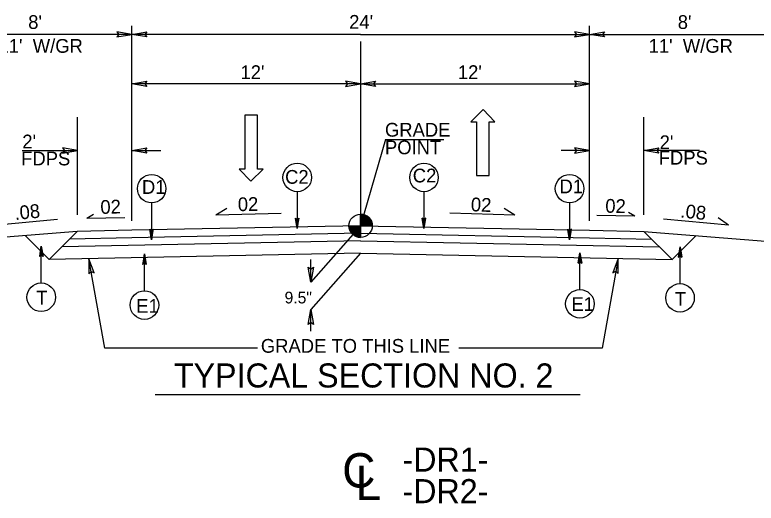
# Model space of a CAD drawing. Extents: x 2532463 to 2534146, y 189689 to 190784.
# Drawn here: x 2533259.8 to 2533701.3, y 189974.2 to 190265.3 of the extents above; entities that cross this region are included whole.
import ezdxf

# ---------------------------------------------------------------- set-up
doc = ezdxf.new("R2010")
doc.units = 0
for name, color, linetype in [('Old_Level_1', 7, 'Continuous'), ('Old_Level_12', 7, 'Continuous'), ('Old_Level_2', 7, 'Continuous'), ('Old_Level_3', 7, 'Continuous'), ('Old_Level_4', 7, 'Continuous'), ('Typical Curb CELL', 7, 'Continuous')]:
    doc.layers.add(name, color=color, linetype=linetype)

msp = doc.modelspace()

# ---------------------------------------------------------------- linework, layer by layer
at = {"layer": 'Old_Level_1'}
for p, q in [((2533465.73, 190146.49), (2533465.72, 190139.54)), ((2533465.72, 190139.54), (2533465.73, 190146.49)), ((2533427.97, 190137.84), (2533426.87, 190144.08)), ((2533426.87, 190144.08), (2533427.97, 190143.26)), ((2533427.03, 190143.96), (2533427.97, 190137.84)), ((2533427.97, 190137.84), (2533427.19, 190143.84)), ((2533427.34, 190143.72), (2533427.97, 190137.84)), ((2533427.97, 190137.84), (2533427.5, 190143.61)), ((2533427.66, 190143.5), (2533427.97, 190137.84)), ((2533427.97, 190137.84), (2533427.81, 190143.38)), ((2533427.97, 190137.84), (2533429.07, 190144.08)), ((2533427.97, 190143.26), (2533429.07, 190144.08)), ((2533427.97, 190137.84), (2533428.92, 190143.96)), ((2533428.76, 190143.84), (2533427.97, 190137.84)), ((2533427.97, 190137.84), (2533428.6, 190143.73)), ((2533428.44, 190143.61), (2533427.97, 190137.84)), ((2533427.97, 190137.84), (2533428.29, 190143.5)), ((2533428.13, 190143.38), (2533427.97, 190137.84)), ((2533427.97, 190143.26), (2533427.97, 190137.84)), ((2533503.48, 190137.84), (2533502.38, 190144.08)), ((2533503.48, 190143.26), (2533502.38, 190144.08)), ((2533503.48, 190137.84), (2533502.53, 190143.96)), ((2533502.69, 190143.84), (2533503.48, 190137.84)), ((2533503.48, 190137.84), (2533502.85, 190143.73)), ((2533503.01, 190143.61), (2533503.48, 190137.84)), ((2533503.48, 190137.84), (2533503.16, 190143.5)), ((2533503.32, 190143.38), (2533503.48, 190137.84)), ((2533503.48, 190137.84), (2533504.58, 190144.08)), ((2533504.58, 190144.08), (2533503.48, 190143.26)), ((2533504.42, 190143.96), (2533503.48, 190137.84)), ((2533503.48, 190137.84), (2533504.26, 190143.84)), ((2533504.11, 190143.72), (2533503.48, 190137.84)), ((2533503.48, 190137.84), (2533503.95, 190143.61)), ((2533503.79, 190143.5), (2533503.48, 190137.84)), ((2533503.48, 190137.84), (2533503.64, 190143.38)), ((2533503.48, 190143.26), (2533503.48, 190137.84)), ((2533465.72, 190139.54), (2533329.41, 190136.82)), ((2533458.78, 190139.54), (2533465.72, 190139.54)), ((2533465.72, 190139.54), (2533465.72, 190132.6)), ((2533472.67, 190139.54), (2533465.72, 190139.54)), ((2533465.72, 190139.54), (2533602.04, 190136.82)), ((2533296.94, 190136.17), (2533218.42, 190129.89)), ((2533265.91, 190133.69), (2533280.19, 190119.41)), ((2533296.94, 190136.17), (2533280.19, 190119.41)), ((2533329.41, 190136.82), (2533296.94, 190136.17)), ((2533465.72, 190135.03), (2533329.41, 190132.31)), ((2533341.26, 190131.18), (2533340.16, 190137.41)), ((2533340.16, 190137.41), (2533341.26, 190136.6)), ((2533340.32, 190137.3), (2533341.26, 190131.18)), ((2533341.26, 190131.18), (2533340.47, 190137.18)), ((2533340.63, 190137.06), (2533341.26, 190131.18)), ((2533341.26, 190131.18), (2533340.79, 190136.95)), ((2533340.94, 190136.84), (2533341.26, 190131.18)), ((2533341.26, 190131.18), (2533341.1, 190136.72)), ((2533341.26, 190131.18), (2533342.36, 190137.41)), ((2533341.26, 190136.6), (2533342.36, 190137.41)), ((2533341.26, 190131.18), (2533342.2, 190137.3)), ((2533342.04, 190137.18), (2533341.26, 190131.18)), ((2533341.26, 190131.18), (2533341.89, 190137.06)), ((2533341.73, 190136.95), (2533341.26, 190131.18)), ((2533341.26, 190131.18), (2533341.57, 190136.84)), ((2533341.42, 190136.72), (2533341.26, 190131.18)), ((2533341.26, 190136.6), (2533341.26, 190131.18)), ((2533465.72, 190135.03), (2533602.04, 190132.31)), ((2533590.19, 190131.18), (2533589.09, 190137.41)), ((2533590.19, 190136.6), (2533589.09, 190137.41)), ((2533590.19, 190131.18), (2533589.25, 190137.3)), ((2533589.4, 190137.18), (2533590.19, 190131.18)), ((2533590.19, 190131.18), (2533589.56, 190137.06)), ((2533589.72, 190136.95), (2533590.19, 190131.18)), ((2533590.19, 190131.18), (2533589.88, 190136.84)), ((2533590.03, 190136.72), (2533590.19, 190131.18)), ((2533590.19, 190131.18), (2533591.29, 190137.41)), ((2533591.29, 190137.41), (2533590.19, 190136.6)), ((2533591.13, 190137.3), (2533590.19, 190131.18)), ((2533590.19, 190131.18), (2533590.97, 190137.18)), ((2533590.82, 190137.06), (2533590.19, 190131.18)), ((2533590.19, 190131.18), (2533590.66, 190136.95)), ((2533590.51, 190136.84), (2533590.19, 190131.18)), ((2533590.19, 190131.18), (2533590.35, 190136.72)), ((2533590.19, 190136.6), (2533590.19, 190131.18)), ((2533602.04, 190136.82), (2533634.51, 190136.17)), ((2533634.51, 190136.17), (2533651.26, 190119.41)), ((2533634.51, 190136.17), (2533713.02, 190129.89)), ((2533665.53, 190133.69), (2533651.26, 190119.41)), ((2533465.72, 190130.56), (2533287.77, 190127)), ((2533329.41, 190132.34), (2533292.37, 190131.6)), ((2533465.72, 190130.56), (2533643.68, 190127)), ((2533602.04, 190132.34), (2533639.08, 190131.6)), ((2533275.46, 190127.42), (2533274.36, 190121.19)), ((2533275.46, 190127.42), (2533274.51, 190121.3)), ((2533274.67, 190121.42), (2533275.46, 190127.42)), ((2533275.46, 190127.42), (2533274.83, 190121.54)), ((2533274.99, 190121.65), (2533275.46, 190127.42)), ((2533275.46, 190127.42), (2533275.14, 190121.76)), ((2533275.3, 190121.88), (2533275.46, 190127.42)), ((2533275.46, 190127.42), (2533276.56, 190121.18)), ((2533276.4, 190121.3), (2533275.46, 190127.42)), ((2533275.46, 190127.42), (2533276.24, 190121.42)), ((2533276.08, 190121.54), (2533275.46, 190127.42)), ((2533275.46, 190127.42), (2533275.93, 190121.65)), ((2533275.77, 190121.76), (2533275.46, 190127.42)), ((2533275.46, 190127.42), (2533275.61, 190121.88)), ((2533275.46, 190122), (2533275.46, 190127.42)), ((2533655.99, 190127.04), (2533654.89, 190120.81)), ((2533655.05, 190120.93), (2533655.99, 190127.04)), ((2533655.99, 190127.04), (2533655.21, 190121.05)), ((2533655.36, 190121.16), (2533655.99, 190127.04)), ((2533655.99, 190127.04), (2533655.52, 190121.28)), ((2533655.68, 190121.39), (2533655.99, 190127.04)), ((2533655.99, 190127.04), (2533655.83, 190121.5)), ((2533655.99, 190127.04), (2533657.09, 190120.81)), ((2533655.99, 190121.62), (2533655.99, 190127.04)), ((2533656.15, 190121.5), (2533655.99, 190127.04)), ((2533655.99, 190127.04), (2533656.31, 190121.39)), ((2533656.46, 190121.28), (2533655.99, 190127.04)), ((2533655.99, 190127.04), (2533656.62, 190121.16)), ((2533656.78, 190121.05), (2533655.99, 190127.04)), ((2533655.99, 190127.04), (2533656.94, 190120.93)), ((2533275.46, 190122), (2533274.36, 190121.19)), ((2533276.56, 190121.18), (2533275.46, 190122)), ((2533465.72, 190123.13), (2533280.19, 190119.41)), ((2533336.98, 190122.73), (2533335.88, 190116.5)), ((2533336.98, 190122.73), (2533336.03, 190116.61)), ((2533336.19, 190116.73), (2533336.98, 190122.73)), ((2533336.98, 190122.73), (2533336.35, 190116.85)), ((2533336.51, 190116.96), (2533336.98, 190122.73)), ((2533336.98, 190122.73), (2533336.66, 190117.07)), ((2533336.82, 190117.19), (2533336.98, 190122.73)), ((2533336.98, 190122.73), (2533338.08, 190116.5)), ((2533337.92, 190116.61), (2533336.98, 190122.73)), ((2533336.98, 190122.73), (2533337.76, 190116.73)), ((2533337.6, 190116.85), (2533336.98, 190122.73)), ((2533336.98, 190122.73), (2533337.45, 190116.96)), ((2533337.29, 190117.07), (2533336.98, 190122.73)), ((2533336.98, 190122.73), (2533337.13, 190117.19)), ((2533336.98, 190117.31), (2533336.98, 190122.73)), ((2533465.72, 190123.13), (2533651.26, 190119.41)), ((2533596.35, 190123.48), (2533595.25, 190117.25)), ((2533595.41, 190117.36), (2533596.35, 190123.48)), ((2533596.35, 190123.48), (2533595.56, 190117.48)), ((2533595.72, 190117.6), (2533596.35, 190123.48)), ((2533596.35, 190123.48), (2533595.88, 190117.71)), ((2533596.03, 190117.82), (2533596.35, 190123.48)), ((2533596.35, 190123.48), (2533596.19, 190117.94)), ((2533596.35, 190123.48), (2533597.45, 190117.25)), ((2533596.35, 190118.06), (2533596.35, 190123.48)), ((2533596.51, 190117.94), (2533596.35, 190123.48)), ((2533596.35, 190123.48), (2533596.66, 190117.82)), ((2533596.82, 190117.71), (2533596.35, 190123.48)), ((2533596.35, 190123.48), (2533596.98, 190117.6)), ((2533597.13, 190117.48), (2533596.35, 190123.48)), ((2533596.35, 190123.48), (2533597.29, 190117.36)), ((2533654.89, 190120.81), (2533655.99, 190121.62)), ((2533655.99, 190121.62), (2533657.09, 190120.81)), ((2533336.98, 190117.31), (2533335.88, 190116.5)), ((2533338.08, 190116.5), (2533336.98, 190117.31)), ((2533595.25, 190117.25), (2533596.35, 190118.06)), ((2533596.35, 190118.06), (2533597.45, 190117.25)), ((2533343.32, 190039), (2533596.51, 190039))]:
    msp.add_line(p, q, dxfattribs=at)
for points in [[(2533465.82, 190139.54), (2533465.82, 190146.49), (2533465.82, 190146.49)], [(2533465.96, 190139.54), (2533465.96, 190146.48)], [(2533466.1, 190139.54), (2533466.1, 190146.47)], [(2533466.24, 190139.54), (2533466.24, 190146.47)], [(2533466.37, 190139.54), (2533466.38, 190146.46)], [(2533466.52, 190139.54), (2533466.52, 190146.44)], [(2533466.65, 190139.54), (2533466.65, 190146.43)], [(2533466.8, 190139.54), (2533466.8, 190146.4)], [(2533466.93, 190139.54), (2533466.93, 190146.38)], [(2533467.07, 190139.54), (2533467.07, 190146.36)], [(2533467.21, 190139.54), (2533467.21, 190146.33)], [(2533467.35, 190139.54), (2533467.35, 190146.29)], [(2533467.49, 190139.54), (2533467.49, 190146.26)], [(2533467.63, 190139.54), (2533467.63, 190146.22)], [(2533467.77, 190139.54), (2533467.77, 190146.18)], [(2533467.9, 190139.54), (2533467.9, 190146.14)], [(2533468.04, 190139.54), (2533468.04, 190146.09)], [(2533468.18, 190139.54), (2533468.18, 190146.04)], [(2533468.32, 190139.54), (2533468.32, 190145.98)], [(2533468.46, 190139.54), (2533468.46, 190145.93)], [(2533468.6, 190139.54), (2533468.6, 190145.86)], [(2533468.74, 190139.54), (2533468.74, 190145.8)], [(2533468.88, 190139.54), (2533468.88, 190145.73)], [(2533469.02, 190139.54), (2533469.02, 190145.66)], [(2533469.15, 190139.54), (2533469.15, 190145.58)], [(2533469.29, 190139.54), (2533469.3, 190145.5)], [(2533469.43, 190139.54), (2533469.43, 190145.41)], [(2533469.57, 190139.54), (2533469.57, 190145.32)], [(2533469.71, 190139.54), (2533469.71, 190145.23)], [(2533469.85, 190139.54), (2533469.85, 190145.13)], [(2533469.99, 190139.54), (2533469.99, 190145.02)], [(2533470.13, 190139.54), (2533470.13, 190144.91)], [(2533470.26, 190139.54), (2533470.27, 190144.79)], [(2533470.4, 190139.54), (2533470.4, 190144.67)], [(2533470.54, 190139.54), (2533470.55, 190144.54)], [(2533470.68, 190139.54), (2533470.68, 190144.4)], [(2533470.82, 190139.54), (2533470.82, 190144.26)], [(2533470.96, 190139.54), (2533470.96, 190144.1)], [(2533471.1, 190139.54), (2533471.1, 190143.94)], [(2533471.23, 190139.54), (2533471.23, 190143.76)], [(2533471.38, 190139.54), (2533471.38, 190143.58)], [(2533471.51, 190139.54), (2533471.51, 190143.37)], [(2533471.66, 190139.54), (2533471.66, 190143.15)], [(2533471.79, 190139.54), (2533471.79, 190142.92)], [(2533471.93, 190139.54), (2533471.93, 190142.66)], [(2533472.07, 190139.54), (2533472.07, 190142.36)], [(2533472.21, 190139.54), (2533472.21, 190142.02)], [(2533458.85, 190138.56), (2533458.85, 190139.54)], [(2533458.99, 190137.86), (2533458.99, 190139.55)], [(2533459.13, 190137.38), (2533459.13, 190139.55)], [(2533459.27, 190136.99), (2533459.27, 190139.54)], [(2533459.4, 190136.67), (2533459.41, 190139.55)], [(2533459.55, 190136.37), (2533459.55, 190139.55)], [(2533459.68, 190136.12), (2533459.68, 190139.54)], [(2533459.82, 190135.89), (2533459.82, 190139.55)], [(2533459.96, 190135.67), (2533459.96, 190139.55)], [(2533460.1, 190135.47), (2533460.1, 190139.54)], [(2533460.24, 190135.29), (2533460.24, 190139.55)], [(2533460.38, 190135.12), (2533460.38, 190139.55)], [(2533460.52, 190134.95), (2533460.52, 190139.54)], [(2533460.65, 190134.8), (2533460.65, 190139.55)], [(2533460.8, 190134.66), (2533460.8, 190139.55)], [(2533460.93, 190134.52), (2533460.93, 190139.54)], [(2533461.07, 190134.39), (2533461.07, 190139.55)], [(2533461.21, 190134.27), (2533461.21, 190139.54)], [(2533461.35, 190134.15), (2533461.35, 190139.54)], [(2533461.49, 190134.04), (2533461.49, 190139.54)], [(2533461.63, 190133.94), (2533461.63, 190139.54)], [(2533461.77, 190133.84), (2533461.77, 190139.54)], [(2533461.91, 190133.75), (2533461.9, 190139.54)], [(2533462.04, 190133.65), (2533462.05, 190139.54)], [(2533462.18, 190133.57), (2533462.18, 190139.54)], [(2533462.32, 190133.49), (2533462.33, 190139.54)], [(2533462.46, 190133.42), (2533462.46, 190139.54)], [(2533462.6, 190133.34), (2533462.6, 190139.54)], [(2533462.74, 190133.27), (2533462.74, 190139.54)], [(2533462.88, 190133.21), (2533462.88, 190139.54)], [(2533463.01, 190133.15), (2533463.02, 190139.54)], [(2533463.16, 190133.09), (2533463.16, 190139.54)], [(2533463.29, 190133.04), (2533463.3, 190139.54)], [(2533463.43, 190132.99), (2533463.43, 190139.54)], [(2533463.57, 190132.94), (2533463.57, 190139.54)], [(2533463.71, 190132.9), (2533463.71, 190139.54)], [(2533463.85, 190132.86), (2533463.85, 190139.54)], [(2533463.99, 190132.82), (2533463.99, 190139.54)], [(2533464.13, 190132.79), (2533464.13, 190139.54)], [(2533464.26, 190132.75), (2533464.27, 190139.54)], [(2533464.41, 190132.73), (2533464.41, 190139.54)], [(2533464.54, 190132.7), (2533464.55, 190139.54)], [(2533464.68, 190132.68), (2533464.68, 190139.54)], [(2533464.82, 190132.66), (2533464.82, 190139.54)], [(2533464.96, 190132.64), (2533464.96, 190139.54)], [(2533465.1, 190132.63), (2533465.1, 190139.54)], [(2533465.24, 190132.62), (2533465.24, 190139.54)], [(2533465.38, 190132.61), (2533465.38, 190139.54)], [(2533465.51, 190132.61), (2533465.52, 190139.54)], [(2533465.66, 190132.6), (2533465.66, 190132.6), (2533465.66, 190139.54)], [(2533472.35, 190139.54), (2533472.35, 190141.62)], [(2533472.49, 190139.54), (2533472.49, 190141.12)], [(2533472.63, 190139.54), (2533472.63, 190140.3)]]:
    msp.add_lwpolyline(points, dxfattribs=at)
msp.add_circle((2533465.72, 190139.54), 6.94, dxfattribs=at)
for start, end in [(359.9906, 89.9906), (179.9906, 269.9906)]:
    msp.add_arc((2533465.72, 190139.54), 6.94, start, end, dxfattribs=at)
at = {"layer": 'Old_Level_2'}
for p, q in [((2533329.41, 190142.51), (2533329.41, 190258.79)), ((2533602.04, 190142.51), (2533602.04, 190258.79)), ((2533329.41, 190253.64), (2533218.47, 190253.64)), ((2533465.73, 190253.64), (2533329.41, 190253.64)), ((2533465.72, 190253.64), (2533602.04, 190253.64)), ((2533602.04, 190253.64), (2533712.98, 190253.64)), ((2533465.72, 190249.32), (2533465.72, 190135.51)), ((2533465.72, 190224.14), (2533329.41, 190224.14)), ((2533465.72, 190224.14), (2533602.04, 190224.14)), ((2533297.01, 190146.14), (2533297.01, 190204.24)), ((2533634.44, 190146.14), (2533634.44, 190204.24)), ((2533480.58, 190190.96), (2533465.72, 190139.54)), ((2533480.58, 190190.96), (2533515.33, 190190.96)), ((2533264.13, 190184.44), (2533297.01, 190184.44)), ((2533329.41, 190184.44), (2533346.69, 190184.44)), ((2533602.04, 190184.44), (2533585.16, 190184.44)), ((2533667.64, 190184.44), (2533634.44, 190184.44)), ((2533427.97, 190159.82), (2533427.97, 190137.84)), ((2533503.48, 190159.82), (2533503.48, 190137.84)), ((2533341.26, 190153.15), (2533341.26, 190131.18)), ((2533590.19, 190153.15), (2533590.19, 190131.18)), ((2533379.53, 190146.05), (2533386.03, 190150.04)), ((2533379.53, 190146.05), (2533418.38, 190147.08)), ((2533557.62, 190145.78), (2533518.78, 190147.1)), ((2533557.62, 190145.78), (2533551.15, 190149.82)), ((2533246.54, 190139.83), (2533285.23, 190143.43)), ((2533684.91, 190139.83), (2533646.22, 190143.43)), ((2533684.91, 190139.83), (2533678.69, 190144.24)), ((2533465.72, 190139.54), (2533436.02, 190105.93)), ((2533275.46, 190105.44), (2533275.46, 190127.42)), ((2533655.99, 190105.07), (2533655.99, 190127.04)), ((2533336.98, 190100.76), (2533336.98, 190122.73)), ((2533465.72, 190123.13), (2533436.02, 190089.52)), ((2533596.35, 190101.51), (2533596.35, 190123.48)), ((2533619.16, 190120.06), (2533609.62, 190066.62)), ((2533313.4, 190066.62), (2533303.9, 190119.89)), ((2533436.02, 190105.93), (2533436.02, 190119.38)), ((2533436.02, 190076.64), (2533436.02, 190089.52)), ((2533404.4, 190066.62), (2533313.4, 190066.62)), ((2533609.62, 190066.62), (2533524.25, 190066.62))]:
    msp.add_line(p, q, dxfattribs=at)
for centre in [(2533427.97, 190168.32), (2533503.48, 190168.32), (2533341.26, 190161.66), (2533590.19, 190161.66), (2533275.46, 190096.94), (2533655.99, 190096.57), (2533336.98, 190092.25), (2533596.35, 190093)]:
    msp.add_circle(centre, 8.5, dxfattribs=at)
at = {"layer": 'Old_Level_3'}
for p, q in [((2533329.41, 190253.64), (2533320.5, 190255.21)), ((2533320.5, 190255.21), (2533321.67, 190253.64)), ((2533320.5, 190252.07), (2533329.41, 190253.64)), ((2533321.67, 190253.64), (2533320.5, 190252.07)), ((2533329.41, 190253.64), (2533338.32, 190255.21)), ((2533338.32, 190252.07), (2533329.41, 190253.64)), ((2533338.32, 190255.21), (2533337.16, 190253.64)), ((2533337.16, 190253.64), (2533338.32, 190252.07)), ((2533602.04, 190253.64), (2533593.13, 190255.21)), ((2533593.13, 190255.21), (2533594.29, 190253.64)), ((2533593.13, 190252.07), (2533602.04, 190253.64)), ((2533594.29, 190253.64), (2533593.13, 190252.07)), ((2533602.04, 190253.64), (2533610.94, 190255.21)), ((2533610.94, 190252.07), (2533602.04, 190253.64)), ((2533610.94, 190255.21), (2533609.78, 190253.64)), ((2533609.78, 190253.64), (2533610.94, 190252.07)), ((2533329.41, 190224.14), (2533338.32, 190225.71)), ((2533338.32, 190222.57), (2533329.41, 190224.14)), ((2533338.32, 190225.71), (2533337.16, 190224.14)), ((2533337.16, 190224.14), (2533338.32, 190222.57)), ((2533465.73, 190224.14), (2533456.82, 190225.71)), ((2533456.82, 190225.71), (2533457.98, 190224.14)), ((2533456.82, 190222.57), (2533465.73, 190224.14)), ((2533457.98, 190224.14), (2533456.82, 190222.57)), ((2533465.72, 190224.14), (2533474.63, 190225.71)), ((2533474.63, 190222.57), (2533465.72, 190224.14)), ((2533474.63, 190225.71), (2533473.47, 190224.14)), ((2533473.47, 190224.14), (2533474.63, 190222.57)), ((2533602.04, 190224.14), (2533593.13, 190225.71)), ((2533593.13, 190225.71), (2533594.29, 190224.14)), ((2533593.13, 190222.57), (2533602.04, 190224.14)), ((2533594.29, 190224.14), (2533593.13, 190222.57)), ((2533297.01, 190184.44), (2533288.1, 190186.01)), ((2533288.1, 190186.01), (2533289.27, 190184.44)), ((2533288.1, 190182.87), (2533297.01, 190184.44)), ((2533289.27, 190184.44), (2533288.1, 190182.87)), ((2533329.41, 190184.44), (2533338.32, 190186.01)), ((2533338.32, 190182.87), (2533329.41, 190184.44)), ((2533338.32, 190186.01), (2533337.16, 190184.44)), ((2533337.16, 190184.44), (2533338.32, 190182.87)), ((2533602.04, 190184.44), (2533593.13, 190186.01)), ((2533593.13, 190186.01), (2533594.29, 190184.44)), ((2533593.13, 190182.87), (2533602.04, 190184.44)), ((2533594.29, 190184.44), (2533593.13, 190182.87)), ((2533634.44, 190184.44), (2533643.34, 190186.01)), ((2533643.34, 190182.87), (2533634.44, 190184.44)), ((2533643.34, 190186.01), (2533642.18, 190184.44)), ((2533642.18, 190184.44), (2533643.34, 190182.87)), ((2533619.16, 190120.06), (2533616.05, 190111.57)), ((2533619.14, 190111.01), (2533619.16, 190120.06)), ((2533307.01, 190111.4), (2533303.9, 190119.89)), ((2533303.9, 190119.89), (2533303.92, 190110.85)), ((2533303.92, 190110.85), (2533305.26, 190112.26)), ((2533305.26, 190112.26), (2533307.01, 190111.4)), ((2533436.02, 190105.93), (2533434.44, 190114.84)), ((2533434.44, 190114.84), (2533436.02, 190113.68)), ((2533437.59, 190114.84), (2533436.02, 190105.93)), ((2533436.02, 190113.68), (2533437.59, 190114.84)), ((2533616.05, 190111.57), (2533617.8, 190112.43)), ((2533617.8, 190112.43), (2533619.14, 190111.01)), ((2533434.45, 190080.61), (2533436.02, 190089.52)), ((2533436.02, 190089.52), (2533437.59, 190080.61)), ((2533436.02, 190081.77), (2533434.45, 190080.61)), ((2533437.59, 190080.61), (2533436.02, 190081.77))]:
    msp.add_line(p, q, dxfattribs=at)
at = {"layer": 'Old_Level_4'}
for p, q in [((2533538.65, 190208.78), (2533531.31, 190201.55)), ((2533545.77, 190201.56), (2533538.65, 190208.78)), ((2533396.74, 190205.41), (2533396.75, 190173.28)), ((2533404.32, 190205.41), (2533396.74, 190205.41)), ((2533404.33, 190173.28), (2533404.32, 190205.41)), ((2533531.31, 190201.55), (2533534.75, 190201.55)), ((2533534.75, 190201.55), (2533534.76, 190169.42)), ((2533542.34, 190169.43), (2533542.32, 190201.56)), ((2533542.32, 190201.56), (2533545.77, 190201.56)), ((2533396.75, 190173.28), (2533393.31, 190173.28)), ((2533393.31, 190173.28), (2533400.43, 190166.05)), ((2533400.43, 190166.05), (2533407.77, 190173.29)), ((2533407.77, 190173.29), (2533404.33, 190173.28)), ((2533534.76, 190169.42), (2533542.34, 190169.43))]:
    msp.add_line(p, q, dxfattribs=at)
at = {"layer": 'Typical Curb CELL'}
for p, q in [((2533629.03, 190145.19), (2533625.23, 190147.49)), ((2533302.71, 190144.07), (2533306.52, 190146.37)), ((2533302.71, 190144.07), (2533325.36, 190144.52)), ((2533629.03, 190145.19), (2533606.38, 190145.64))]:
    msp.add_line(p, q, dxfattribs=at)

# ---------------------------------------------------------------- texts
at = {"layer": 'Old_Level_12'}
for s, height, rotation, p in [("24'", 8.201, 0.0001, (2533458.91, 190256.96)), ("12'", 8.201, 359.9999, (2533394.18, 190226.98)), ("12'", 8.201, 0.0001, (2533523.66, 190226.98)), ('C2', 8.201, 0.0001, (2533496.81, 190165.36)), ('C2', 8.201, 359.9999, (2533420.75, 190164.56)), ('D1', 8.201, 359.9999, (2533335.49, 190158.53)), ('D1', 8.201, 359.9999, (2533584.2, 190158.9)), ('T', 8.2, 359.9999, (2533272.55, 190092.59)), ('T', 8.2, 0.0001, (2533652.94, 190091.84)), ('E1', 8.201, 359.9999, (2533332.09, 190087.63)), ('E1', 8.201, 359.9999, (2533591.3, 190088.76)), ('GRADE TO THIS LINE', 8.2009, 0.0001, (2533406.31, 190063.83))]:
    msp.add_text(s, height=height, rotation=rotation, dxfattribs=at).set_placement(p)
at = {"layer": 'Old_Level_2'}
for s, height, rotation, p in [("8'", 8.201, 359.9999, (2533267.72, 190256.85)), ("8'", 8.201, 0.0001, (2533654.64, 190256.85)), ("11'  W/GR", 8.201, 359.9999, (2533250.04, 190242.63)), ("11'  W/GR", 8.201, 0.0001, (2533637.27, 190242.65)), ('GRADE ', 8.201, 0.0001, (2533480.23, 190192.65)), ("2'", 8.201, 359.9999, (2533264.21, 190185.65)), ("2'", 8.201, 0.0001, (2533643.87, 190185.21)), ('POINT', 8.201, 0.0001, (2533480.23, 190182.18)), ('FDPS', 8.201, 359.9999, (2533263.53, 190175.52)), ('FDPS', 8.201, 0.0001, (2533643.31, 190175.99)), ('.08', 8.201, 5.8332, (2533259.98, 190142.91)), ('.08', 8.201, 354.1668, (2533655.96, 190144.49)), ('9.5"', 6.971, 0.0462, (2533420.45, 190093.25))]:
    msp.add_text(s, height=height, rotation=rotation, dxfattribs=at).set_placement(p)
at = {"layer": 'Old_Level_3'}
for s, height, rotation, p in [('02', 8.201, 1.011, (2533392.65, 190148.21)), ('02', 8.201, 357.5752, (2533531.26, 190148.23)), ('02', 8.201, 358.6184, (2533611.4, 190147.36)), ('02', 8.201, 1.5465, (2533310.83, 190146.58)), ('TYPICAL SECTION NO. 2', 14.3518, 0.0001, (2533354.51, 190043.11)), ('-DR1-', 14.352, 0.0001, (2533490.67, 189992.97)), ('C', 20.5, 0.0001, (2533454.75, 189983.48)), ('L', 20.5, 0.0001, (2533462.74, 189976.01)), ('-DR2-', 14.352, 0.0001, (2533490.67, 189974.16))]:
    msp.add_text(s, height=height, rotation=rotation, dxfattribs=at).set_placement(p)

doc.saveas('drawing.dxf')
